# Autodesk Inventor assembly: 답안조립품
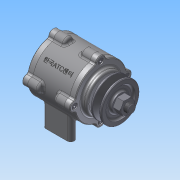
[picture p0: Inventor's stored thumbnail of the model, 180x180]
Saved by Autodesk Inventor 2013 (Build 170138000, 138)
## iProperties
Created: 2015-03
Part Number: 답안조립품
Document SubType Name: Assembly
Designer: Administrator
Author: Administrator
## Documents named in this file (11)
- C:\Documents and Settings\Administrator\바탕 화면\450305V1043\답안조립품.iam
- C:\Documents and Settings\Administrator\바탕 화면\450305V1043\1.본체.ipt
- C:\Documents and Settings\Administrator\바탕 화면\450305V1043\450305V1043\베어링 6204.ipt
- C:\Documents and Settings\Administrator\바탕 화면\450305V1043\450305V1043\축.ipt
- C:\Documents and Settings\Administrator\바탕 화면\450305V1043\450305V1043\V벨트풀리.ipt
- C:\Documents and Settings\Administrator\바탕 화면\450305V1043\450305V1043\키(4 x 4 x 12).ipt
- C:\Documents and Settings\Administrator\바탕 화면\450305V1043\450305V1043\오일실.ipt
- C:\Documents and Settings\Administrator\바탕 화면\450305V1043\450305V1043\커버.ipt
- C:\Documents and Settings\Administrator\바탕 화면\450305V1043\450305V1043\커버2.ipt
- C:\Documents and Settings\Administrator\바탕 화면\450305V1043\450305V1043\너트 M12x1.25.ipt
- C:\Documents and Settings\Administrator\바탕 화면\450305V1043\450305V1043\M 4 x 12.ipt
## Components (15 placed, 7 different names)
1. 1.본체:1
2. KS B 2023 6204 - 20 x 47 x 14:1
3. KS B 2023 6204 - 20 x 47 x 14:2
4. 그루브 풀리1:1 — 각도:2
5. KS B 1311 (I) 4 x 4 x 12:1 — 각도:1, 각도:2
6. KS B 2804 D D - 20 32 8:1
7. KS B 1012 클래스 1 일반 - 미터 M12x1.25:1
8. KS B 1003 - 미터 M 4 x 12:1
9. KS B 1003 - 미터 M 4 x 12:2
10. KS B 1003 - 미터 M 4 x 12:3
11. KS B 1003 - 미터 M 4 x 12:4
12. KS B 1003 - 미터 M 4 x 12:5
13. KS B 1003 - 미터 M 4 x 12:6
14. KS B 1003 - 미터 M 4 x 12:7
15. KS B 1003 - 미터 M 4 x 12:8
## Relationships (2: Angle 2)
- 각도:1 [Angle]: KS B 1311 (I) 4 x 4 x 12:1
- 각도:2 [Angle]: 그루브 풀리1:1 ↔ KS B 1311 (I) 4 x 4 x 12:1
